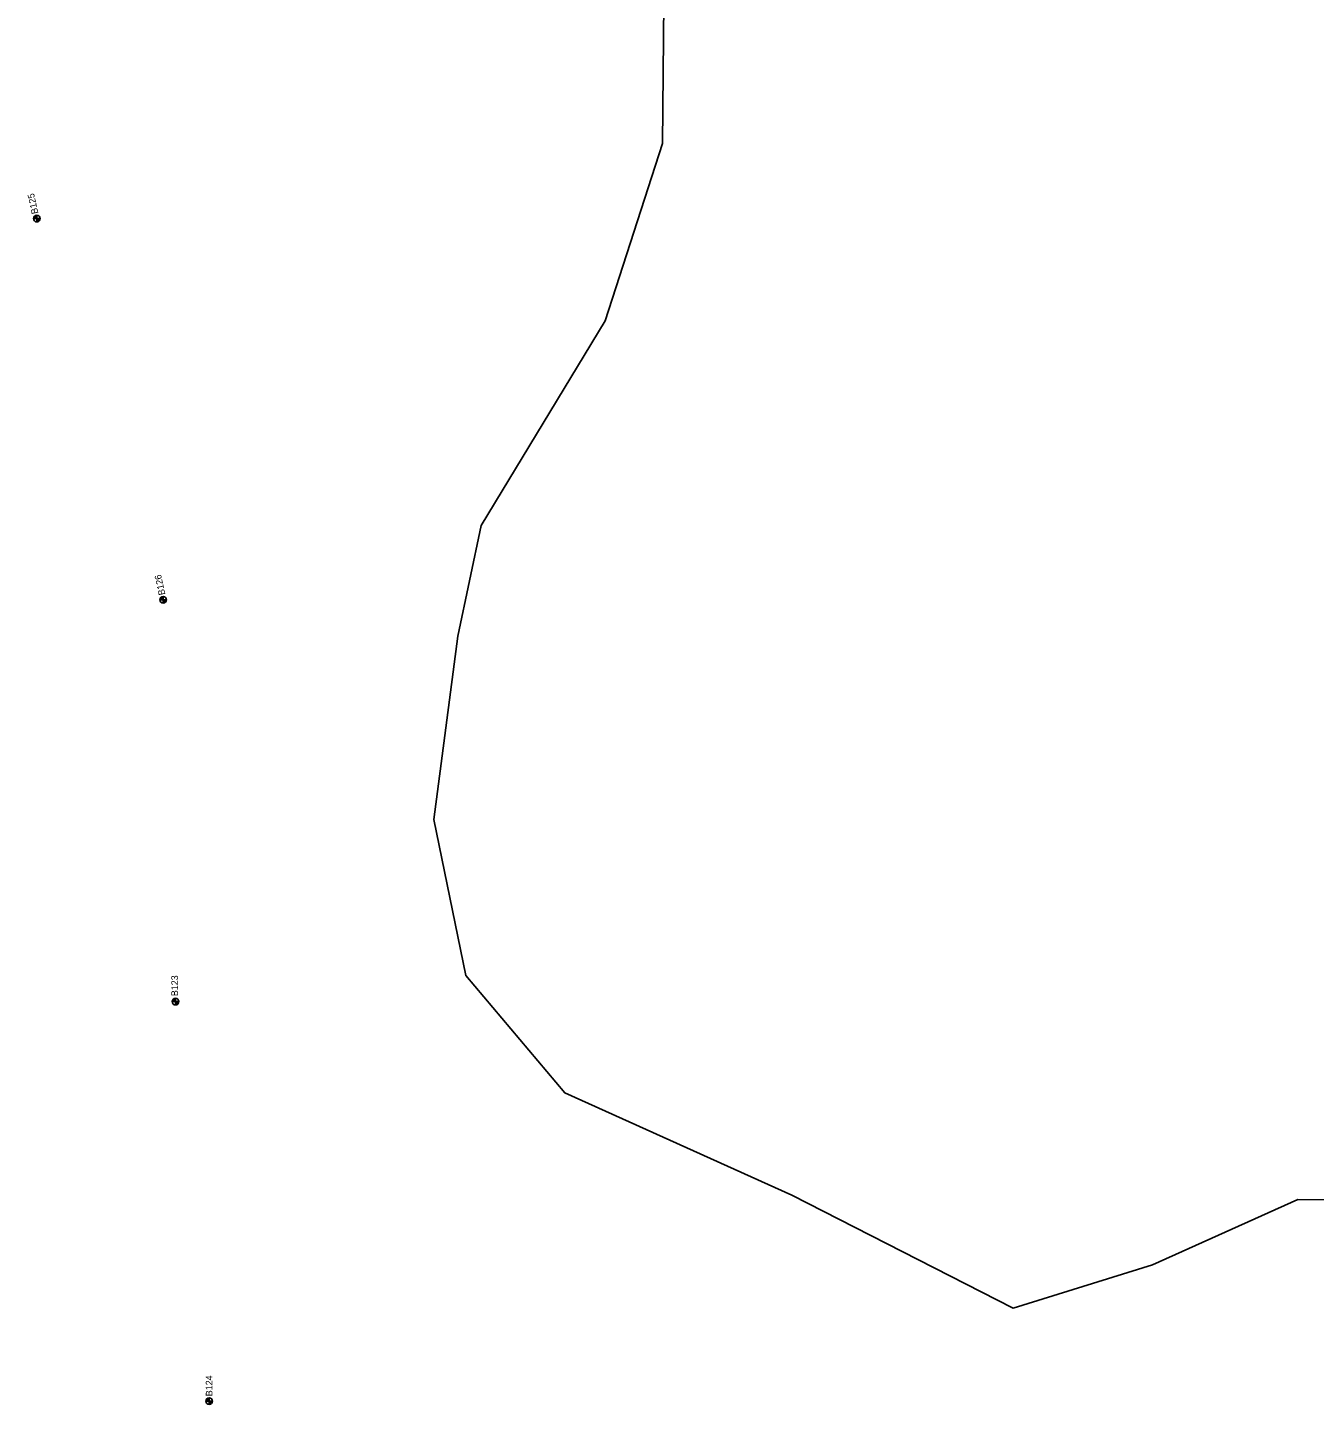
# Model space of a CAD drawing. Extents: x 331323 to 388339, y 121519 to 205315.
# Drawn here: x 356350 to 358280, y 196517 to 198582 of the extents above; entities that cross this region are included whole.
import ezdxf

# ---------------------------------------------------------------- set-up
doc = ezdxf.new("R2010")
doc.units = 0
for name, color, linetype in [('E_SOIL_BORE1 [KAPUR_CADDS_LEVELS]', 7, 'Continuous'), ('E_SOIL_BORE2 [KAPUR_CADDS_LEVELS]', 7, 'Continuous'), ('Level 57', 7, 'Continuous'), ('P_MARK', 7, 'Continuous')]:
    doc.layers.add(name, color=color, linetype=linetype)

msp = doc.modelspace()

# ---------------------------------------------------------------- linework, layer by layer
at = {"layer": 'Level 57'}
msp.add_lwpolyline([(357093.2, 201018.1), (356974, 200752.5), (356988.1, 200477.4), (357101.8, 200143), (357264.4, 199683.2), (357296.6, 199557.9), (357259.2, 199124.9), (357307, 198882.8), (357302.6, 198407.8), (357216.8, 198141.9), (357030.5, 197835.2), (356995.6, 197668.9), (356959.7, 197394.2), (357007.6, 197160.4), (357156.1, 196984.1), (357496.6, 196831), (357828.6, 196661.3), (358037.7, 196726.1), (358255.4, 196824.1), (358480.6, 196822.1), (358630.3, 196770.7), (358712.3, 196620)], dxfattribs=at)
at = {"layer": 'P_MARK'}
for p, q in [((356359.4, 198295.4), (356369.4, 198295.4)), ((356364.4, 198300.4), (356364.4, 198290.4)), ((356548.9, 197723.7), (356558.9, 197723.7)), ((356553.9, 197728.7), (356553.9, 197718.7)), ((356567.3, 197121), (356577.3, 197121)), ((356572.3, 197126), (356572.3, 197116)), ((356617.9, 196521.9), (356627.9, 196521.9)), ((356622.9, 196526.9), (356622.9, 196516.9))]:
    msp.add_line(p, q, dxfattribs=at)
for centre in [(356364.4, 198295.4), (356553.9, 197723.7), (356572.3, 197121), (356622.9, 196521.9)]:
    msp.add_circle(centre, 5, dxfattribs=at)
for centre, radius, start, end in [((356364.4, 198295.4), 4.5, 89.9869, 179.9869), ((356364.4, 198295.4), 4, 89.9869, 179.9869), ((356364.4, 198295.4), 3.5, 89.9869, 179.9869), ((356364.4, 198295.4), 3, 89.9869, 179.9869), ((356364.4, 198295.4), 2.5, 89.9869, 179.9869), ((356364.4, 198295.4), 2, 89.9869, 179.9869), ((356364.4, 198295.4), 1.5, 89.9869, 179.9869), ((356364.4, 198295.4), 1, 89.9869, 179.9869), ((356364.4, 198295.4), 0.5, 89.9869, 179.9869), ((356364.4, 198295.4), 4.5, 269.9869, 359.9869), ((356364.4, 198295.4), 4, 269.9869, 359.9869), ((356364.4, 198295.4), 3.5, 269.9869, 359.9869), ((356364.4, 198295.4), 3, 269.9869, 359.9869), ((356364.4, 198295.4), 2.5, 269.9869, 359.9869), ((356364.4, 198295.4), 2, 269.9869, 359.9869), ((356364.4, 198295.4), 1.5, 269.9869, 359.9869), ((356364.4, 198295.4), 1, 269.9869, 359.9869), ((356364.4, 198295.4), 0.5, 269.9869, 359.9869), ((356553.9, 197723.7), 4.5, 89.9869, 179.9869), ((356553.9, 197723.7), 4, 89.9869, 179.9869), ((356553.9, 197723.7), 3.5, 89.9869, 179.9869), ((356553.9, 197723.7), 3, 89.9869, 179.9869), ((356553.9, 197723.7), 2.5, 89.9869, 179.9869), ((356553.9, 197723.7), 2, 89.9869, 179.9869), ((356553.9, 197723.7), 1.5, 89.9869, 179.9869), ((356553.9, 197723.7), 1, 89.9869, 179.9869), ((356553.9, 197723.7), 0.5, 89.9869, 179.9869), ((356553.9, 197723.7), 4.5, 269.9869, 359.9869), ((356553.9, 197723.7), 4, 269.9869, 359.9869), ((356553.9, 197723.7), 3.5, 269.9869, 359.9869), ((356553.9, 197723.7), 3, 269.9869, 359.9869), ((356553.9, 197723.7), 2.5, 269.9869, 359.9869), ((356553.9, 197723.7), 2, 269.9869, 359.9869), ((356553.9, 197723.7), 1.5, 269.9869, 359.9869), ((356553.9, 197723.7), 1, 269.9869, 359.9869), ((356553.9, 197723.7), 0.5, 269.9869, 359.9869), ((356572.3, 197121), 4.5, 89.9869, 179.9869), ((356572.3, 197121), 4, 89.9869, 179.9869), ((356572.3, 197121), 3.5, 89.9869, 179.9869), ((356572.3, 197121), 3, 89.9869, 179.9869), ((356572.3, 197121), 2.5, 89.9869, 179.9869), ((356572.3, 197121), 2, 89.9869, 179.9869), ((356572.3, 197121), 1.5, 89.9869, 179.9869), ((356572.3, 197121), 1, 89.9869, 179.9869), ((356572.3, 197121), 0.5, 89.9869, 179.9869), ((356572.3, 197121), 4.5, 269.9869, 359.9869), ((356572.3, 197121), 4, 269.9869, 359.9869), ((356572.3, 197121), 3.5, 269.9869, 359.9869), ((356572.3, 197121), 3, 269.9869, 359.9869), ((356572.3, 197121), 2.5, 269.9869, 359.9869), ((356572.3, 197121), 2, 269.9869, 359.9869), ((356572.3, 197121), 1.5, 269.9869, 359.9869), ((356572.3, 197121), 1, 269.9869, 359.9869), ((356572.3, 197121), 0.5, 269.9869, 359.9869), ((356622.9, 196521.9), 4.5, 89.9869, 179.9869), ((356622.9, 196521.9), 4, 89.9869, 179.9869), ((356622.9, 196521.9), 3.5, 89.9869, 179.9869), ((356622.9, 196521.9), 3, 89.9869, 179.9869), ((356622.9, 196521.9), 2.5, 89.9869, 179.9869), ((356622.9, 196521.9), 2, 89.9869, 179.9869), ((356622.9, 196521.9), 1.5, 89.9869, 179.9869), ((356622.9, 196521.9), 1, 89.9869, 179.9869), ((356622.9, 196521.9), 0.5, 89.9869, 179.9869), ((356622.9, 196521.9), 4.5, 269.9869, 359.9869), ((356622.9, 196521.9), 4, 269.9869, 359.9869), ((356622.9, 196521.9), 3.5, 269.9869, 359.9869), ((356622.9, 196521.9), 3, 269.9869, 359.9869), ((356622.9, 196521.9), 2.5, 269.9869, 359.9869), ((356622.9, 196521.9), 2, 269.9869, 359.9869), ((356622.9, 196521.9), 1.5, 269.9869, 359.9869), ((356622.9, 196521.9), 1, 269.9869, 359.9869), ((356622.9, 196521.9), 0.5, 269.9869, 359.9869)]:
    msp.add_arc(centre, radius, start, end, dxfattribs=at)

# ---------------------------------------------------------------- texts
at = {"layer": 'E_SOIL_BORE1 [KAPUR_CADDS_LEVELS]'}
for s, rotation, p in [('B125', 102.6348, (356366.8, 198303.5)), ('B124', 89.9869, (356627.8, 196529.2))]:
    msp.add_text(s, height=10, rotation=rotation, dxfattribs=at).set_placement(p)
at = {"layer": 'E_SOIL_BORE2 [KAPUR_CADDS_LEVELS]'}
for s, rotation, p in [('B126', 102.6348, (356557.3, 197731.8)), ('B123', 89.9869, (356576.1, 197129.2))]:
    msp.add_text(s, height=10, rotation=rotation, dxfattribs=at).set_placement(p)

doc.saveas('drawing.dxf')
